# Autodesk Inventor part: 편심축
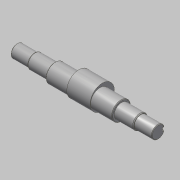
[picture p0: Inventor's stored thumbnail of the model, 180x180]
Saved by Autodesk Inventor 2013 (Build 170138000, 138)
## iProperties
Created: 2015-10
Part Number: 편심축
Document SubType Name: Modeling
Designer: mdu
Density: 7.86 g/cm^3
Material: 강철, 연강
Mass: 1327.93 g
Surface Area: 248.524 cm^2
Volume: 168.947 cm^3
Author: mdu
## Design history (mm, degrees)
sketch "스케치1"
  geometry: L1 (-20.5, -41.331)-(-20.5, 32.669) reference; L2 (7.5, -30.031)-(7.5, 21.369) reference; L3 (135.5, -30.331)-(135.5, 21.669) reference; L4 (121.5, 21.369)-(121.5, -30.031) reference; L5 (184.5, -4.331)-(-57.5, -4.331); L6 (184.5, -4.331)-(184.5, 6.669); L7 (154.5, 8.169)-(121.5, 8.169); L8 (121.5, 8.169)-(121.5, 11.669); L9 (121.5, 11.669)-(7.5, 11.669); L10 (7.5, 11.669)-(7.5, 8.169); L11 (7.5, 8.169)-(-27.5, 8.169); L12 (-27.5, 8.169)-(-27.5, 6.669); L13 (-27.5, 6.669)-(-57.5, 6.669); L14 (-57.5, 6.669)-(-57.5, -4.331); L15 (154.5, 8.169)-(154.5, 6.669); L16 (154.5, 6.669)-(184.5, 6.669); C1 r 32.5 at (64.5, -4.331) reference; 1 further point
  constraints: 24 end point, 8 perpendicular, 5 point on line, 3 parallel, 2 collinear
  dimensions: "d1" = 25 diameter of L11 L5; "d2" = 32 diameter of L9 L5; "d3" = 22 diameter of L13 L5; "d4" = 35 distance of L10.end L11.end; "d5" = 30 distance of L12.end L13.end; "d15" = 33 distance of L7.start L7.end; "d26" = 30 distance of L15.end L6.end
revolve "회전1" sketch "스케치1" stored, may be unused: angle "d6" = 90 deg
node "작업 평면1"
sketch "스케치2"
  geometry: C1 r 16 at (0, 0) reference; C2 r 16 at (0, 0) reference; C3 r 20.75 at (0, 4); C4 r 16 at (0, 0) reference; 1 further point
  constraints: 1 centre point, 1 vertical alignment
  dimensions: "d8" = 41.5 diameter of C3; "d25" = 4 distance of C3.centre C1.centre
extrude "돌출1" join sketch "스케치2" stored distance "d9" = 40; taper "d10" = 0 deg
chamfer "모따기1" distance "d11" = 1; stored, may be unused: second distance "d12" = 2, angle "d13" = 45 deg
node "작업 평면2"
sketch "스케치3"
  geometry: L1 (-15, -10)-(-15, 10) reference; L2 (-15, 3)-(0, 3); L3 (0, -3)-(-15, -3); A1 r 3 centre (0, 0) between (0, -3) and (0, 3); 2 further points
  constraints: 4 end point, 2 perpendicular, 2 point on circle, 2 point on line, 2 tangent, 1 centre point, 1 horizontal alignment, 1 midpoint
  dimensions: "d16" = 18 dimension on A1 L1; "d17" = 6 distance between parallel lines of L3 L2
extrude "돌출2" cut sketch "스케치3" distance "d18" = 3.5; taper "d19" = 0 deg
node "작업 평면3"
chamfer "모따기2" distance "d27" = 1.5; stored, may be unused: second distance "d28" = 2, angle "d29" = 30 deg
chamfer "모따기3" distance "d30" = 1.5; stored, may be unused: second distance "d31" = 2, angle "d32" = 30 deg
node "솔리드1"
mirror "대칭1"
node "참조1"
node "참조2"
node "참조3"
node "참조4"
node "참조5"
node "투영된 루프1"
